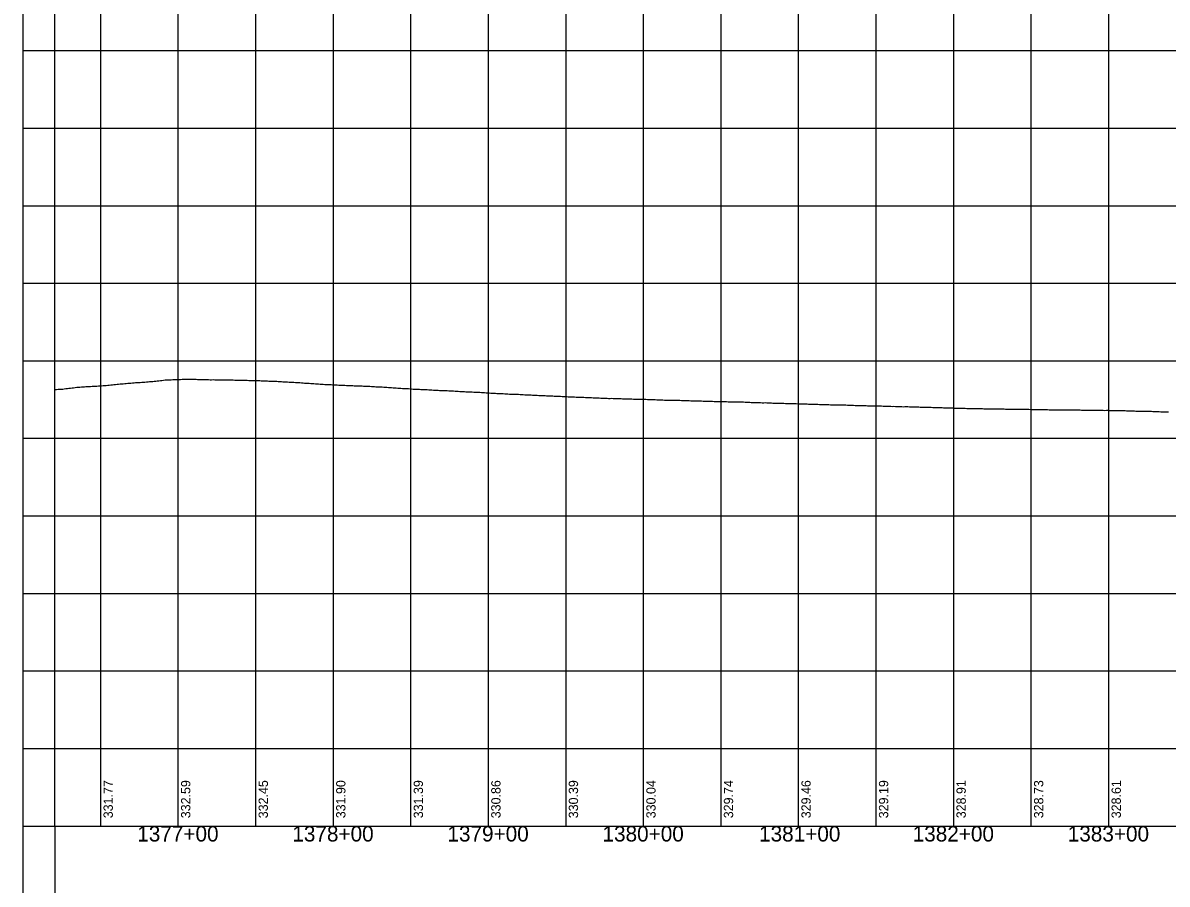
# Model space of a CAD drawing. Extents: x -90830 to 2015517, y -20856 to 836331.
# Drawn here: x 9623 to 10361, y 20025 to 20581 of the extents above; entities that cross this region are included whole.
import ezdxf

# ---------------------------------------------------------------- set-up
doc = ezdxf.new("R2010")
doc.units = 0
for name, color, linetype in [('Level 1', 7, 'Continuous'), ('RD_DDB_Profile_EX', 7, 'Continuous'), ('RD_DDB_StaTX', 7, 'Continuous'), ('RD_DDB_StripGrade', 7, 'Continuous'), ('RD_GPK_Profile_Cell', 7, 'Continuous'), ('RD_SHT_MatchLine', 7, 'Continuous')]:
    doc.layers.add(name, color=color, linetype=linetype)

msp = doc.modelspace()

# ---------------------------------------------------------------- linework, layer by layer
at = {"layer": 'Level 1'}
for p, q in [((9623.46, 21062.87), (9623.46, 20562.87)), ((9673.46, 21062.87), (9673.46, 20562.87)), ((9723.46, 21062.87), (9723.46, 20562.87)), ((9773.46, 21062.87), (9773.46, 20562.87)), ((9823.46, 21062.87), (9823.46, 20562.87)), ((9873.46, 21062.87), (9873.46, 20562.87)), ((9923.46, 21062.87), (9923.46, 20562.87)), ((9973.46, 21062.87), (9973.46, 20562.87)), ((10023.46, 21062.87), (10023.46, 20562.87)), ((10073.46, 21062.87), (10073.46, 20562.87)), ((10123.46, 21062.87), (10123.46, 20562.87)), ((10173.46, 21062.87), (10173.46, 20562.87)), ((10223.46, 21062.87), (10223.46, 20562.87)), ((10273.46, 21062.87), (10273.46, 20562.87)), ((10323.46, 21062.87), (10323.46, 20562.87)), ((9623.46, 20562.87), (11223.46, 20562.87)), ((9623.46, 20562.87), (11223.46, 20562.87)), ((9623.46, 20562.87), (9623.46, 20062.87)), ((9673.46, 20562.87), (9673.46, 20062.87)), ((9723.46, 20562.87), (9723.46, 20062.87)), ((9773.46, 20562.87), (9773.46, 20062.87)), ((9823.46, 20562.87), (9823.46, 20062.87)), ((9873.46, 20562.87), (9873.46, 20062.87)), ((9923.46, 20562.87), (9923.46, 20062.87)), ((9973.46, 20562.87), (9973.46, 20062.87)), ((10023.46, 20562.87), (10023.46, 20062.87)), ((10073.46, 20562.87), (10073.46, 20062.87)), ((10123.46, 20562.87), (10123.46, 20062.87)), ((10173.46, 20562.87), (10173.46, 20062.87)), ((10223.46, 20562.87), (10223.46, 20062.87)), ((10273.46, 20562.87), (10273.46, 20062.87)), ((10323.46, 20562.87), (10323.46, 20062.87)), ((9623.46, 20512.87), (11223.46, 20512.87)), ((9623.46, 20462.87), (11223.46, 20462.87)), ((9623.46, 20412.87), (11223.46, 20412.87)), ((9623.46, 20362.87), (11223.46, 20362.87)), ((9623.46, 20312.87), (11223.46, 20312.87)), ((9623.46, 20262.87), (11223.46, 20262.87)), ((9623.46, 20212.87), (11223.46, 20212.87)), ((9623.46, 20162.87), (11223.46, 20162.87)), ((9623.46, 20112.87), (11223.46, 20112.87)), ((9623.46, 20062.87), (11223.46, 20062.87))]:
    msp.add_line(p, q, dxfattribs=at)
at = {"layer": 'RD_DDB_Profile_EX'}
for points in [[(9644.15, 20344.38), (9645.15, 20344.44), (9646.15, 20344.5), (9647.15, 20344.55), (9648.15, 20344.61), (9649.15, 20344.62), (9650.15, 20344.74), (9651.15, 20344.89), (9652.15, 20344.96), (9653.15, 20345.12), (9654.15, 20345.28), (9655.15, 20345.38), (9656.15, 20345.52), (9657.15, 20345.63), (9658.15, 20345.77), (9659.15, 20345.84), (9660.15, 20345.93), (9661.15, 20346.03), (9662.15, 20346.08), (9663.15, 20346.13), (9664.15, 20346.21), (9665.15, 20346.27), (9666.15, 20346.31), (9667.15, 20346.36), (9668.15, 20346.44), (9669.15, 20346.51), (9670.15, 20346.56), (9671.15, 20346.6), (9672.15, 20346.66), (9673.15, 20346.7), (9674.15, 20346.79), (9675.15, 20346.85), (9676.15, 20346.89), (9677.15, 20346.98), (9678.15, 20347.07), (9679.15, 20347.17), (9680.15, 20347.27), (9681.15, 20347.37), (9682.15, 20347.51), (9683.15, 20347.65), (9684.15, 20347.76), (9685.15, 20347.86), (9686.15, 20347.95), (9687.15, 20348.01), (9688.15, 20348.08), (9689.15, 20348.2), (9690.15, 20348.29), (9691.15, 20348.37), (9692.15, 20348.47), (9693.15, 20348.5), (9694.15, 20348.57), (9695.15, 20348.66), (9696.15, 20348.76), (9697.15, 20348.82), (9698.15, 20348.87), (9699.15, 20348.96), (9700.15, 20349.06), (9701.15, 20349.13), (9702.15, 20349.14), (9703.15, 20349.21), (9704.15, 20349.31), (9705.15, 20349.4), (9706.15, 20349.53), (9707.15, 20349.6), (9708.15, 20349.69), (9709.15, 20349.75), (9710.15, 20349.88), (9711.15, 20350.02), (9712.15, 20350.13), (9713.15, 20350.22), (9714.15, 20350.34), (9715.15, 20350.48), (9716.15, 20350.54), (9717.15, 20350.59), (9718.15, 20350.64), (9719.15, 20350.66), (9720.15, 20350.74), (9721.15, 20350.8), (9722.15, 20350.81), (9723.15, 20350.81), (9724.15, 20350.77), (9725.15, 20350.8), (9726.15, 20351.02), (9727.15, 20351.08), (9728.15, 20351.09), (9729.15, 20351.06), (9730.15, 20351.06), (9731.15, 20351.03), (9732.15, 20350.98), (9733.15, 20350.98), (9734.15, 20350.94), (9735.15, 20350.93), (9736.15, 20350.89), (9737.15, 20350.82), (9738.15, 20350.82), (9739.15, 20350.88), (9740.15, 20350.86), (9741.15, 20350.78), (9742.15, 20350.74), (9743.15, 20350.7), (9744.15, 20350.66)], [(9744.15, 20350.66), (9745.15, 20350.66), (9746.15, 20350.7), (9747.15, 20350.68), (9748.15, 20350.67), (9749.15, 20350.64), (9750.15, 20350.56), (9751.15, 20350.55), (9752.15, 20350.59), (9753.15, 20350.6), (9754.15, 20350.6), (9755.15, 20350.56), (9756.15, 20350.55), (9757.15, 20350.55), (9758.15, 20350.54), (9759.15, 20350.51), (9760.15, 20350.46), (9761.15, 20350.46), (9762.15, 20350.42), (9763.15, 20350.41), (9764.15, 20350.4), (9765.15, 20350.37), (9766.15, 20350.31), (9767.15, 20350.29), (9768.15, 20350.3), (9769.15, 20350.23), (9770.15, 20350.17), (9771.15, 20350.17), (9772.15, 20350.16), (9773.15, 20350.13), (9774.15, 20350.12), (9775.15, 20350.08), (9776.15, 20350.06), (9777.15, 20350.02), (9778.15, 20349.98), (9779.15, 20349.93), (9780.15, 20349.89), (9781.15, 20349.85), (9782.15, 20349.8), (9783.15, 20349.75), (9784.15, 20349.7), (9785.15, 20349.65), (9786.15, 20349.63), (9787.15, 20349.62), (9788.15, 20349.58), (9789.15, 20349.51), (9790.15, 20349.44), (9791.15, 20349.39), (9792.15, 20349.33), (9793.15, 20349.28), (9794.15, 20349.2), (9795.15, 20349.16), (9796.15, 20349.12), (9797.15, 20349.09), (9798.15, 20348.99), (9799.15, 20348.93), (9800.15, 20348.89), (9801.15, 20348.83), (9802.15, 20348.78), (9803.15, 20348.7), (9804.15, 20348.6), (9805.15, 20348.49), (9806.15, 20348.44), (9807.15, 20348.41), (9808.15, 20348.35), (9809.15, 20348.3), (9810.15, 20348.22), (9811.15, 20348.12), (9812.15, 20348.07), (9813.15, 20348.01), (9814.15, 20347.93), (9815.15, 20347.85), (9816.15, 20347.77), (9817.15, 20347.72), (9818.15, 20347.67), (9819.15, 20347.61), (9820.15, 20347.53), (9821.15, 20347.49), (9822.15, 20347.48), (9823.15, 20347.41), (9824.15, 20347.32), (9825.15, 20347.29), (9826.15, 20347.27), (9827.15, 20347.22), (9828.15, 20347.17), (9829.15, 20347.12), (9830.15, 20347.09), (9831.15, 20347.07), (9832.15, 20347.02), (9833.15, 20346.98), (9834.15, 20346.97), (9835.15, 20346.92), (9836.15, 20346.86), (9837.15, 20346.81), (9838.15, 20346.76), (9839.15, 20346.73), (9840.15, 20346.71), (9841.15, 20346.66), (9842.15, 20346.61), (9843.15, 20346.58), (9844.15, 20346.56)], [(9844.15, 20346.56), (9845.15, 20346.51), (9846.15, 20346.46), (9847.15, 20346.41), (9848.15, 20346.36), (9849.15, 20346.31), (9850.15, 20346.24), (9851.15, 20346.16), (9852.15, 20346.09), (9853.15, 20346.01), (9854.15, 20345.97), (9855.15, 20345.96), (9856.15, 20345.91), (9857.15, 20345.84), (9858.15, 20345.76), (9859.15, 20345.69), (9860.15, 20345.62), (9861.15, 20345.58), (9862.15, 20345.46), (9863.15, 20345.42), (9864.15, 20345.39), (9865.15, 20345.31), (9866.15, 20345.26), (9867.15, 20345.19), (9868.15, 20345.09), (9869.15, 20345.01), (9870.15, 20344.97), (9871.15, 20344.96), (9872.15, 20344.91), (9873.15, 20344.84), (9874.15, 20344.74), (9875.15, 20344.66), (9876.15, 20344.61), (9877.15, 20344.57), (9878.15, 20344.56), (9879.15, 20344.49), (9880.15, 20344.41), (9881.15, 20344.37), (9882.15, 20344.36), (9883.15, 20344.31), (9884.15, 20344.26), (9885.15, 20344.19), (9886.15, 20344.11), (9887.15, 20344.06), (9888.15, 20344.01), (9889.15, 20343.94), (9890.15, 20343.87), (9891.15, 20343.84), (9892.15, 20343.76), (9893.15, 20343.72), (9894.15, 20343.72), (9895.15, 20343.71), (9896.15, 20343.66), (9897.15, 20343.61), (9898.15, 20343.54), (9899.15, 20343.46), (9900.15, 20343.42), (9901.15, 20343.39), (9902.15, 20343.31), (9903.15, 20343.26), (9904.15, 20343.21), (9905.15, 20343.16), (9906.15, 20343.11), (9907.15, 20343.06), (9908.15, 20343.01), (9909.15, 20342.94), (9910.15, 20342.86), (9911.15, 20342.82), (9912.15, 20342.81), (9913.15, 20342.76), (9914.15, 20342.71), (9915.15, 20342.66), (9916.15, 20342.61), (9917.15, 20342.56), (9918.15, 20342.52), (9919.15, 20342.49), (9920.15, 20342.39), (9921.15, 20342.31), (9922.15, 20342.26), (9923.15, 20342.19), (9924.15, 20342.11), (9925.15, 20342.06), (9926.15, 20342.01), (9927.15, 20341.96), (9928.15, 20341.91), (9929.15, 20341.86), (9930.15, 20341.81), (9931.15, 20341.76), (9932.15, 20341.71), (9933.15, 20341.66), (9934.15, 20341.59), (9935.15, 20341.52), (9936.15, 20341.49), (9937.15, 20341.41), (9938.15, 20341.39), (9939.15, 20341.41), (9940.15, 20341.34), (9941.15, 20341.27), (9942.15, 20341.29), (9943.15, 20341.27), (9944.15, 20341.14)], [(9944.15, 20341.14), (9945.15, 20341.07), (9946.15, 20341.06), (9947.15, 20341.01), (9948.15, 20340.94), (9949.15, 20340.87), (9950.15, 20340.86), (9951.15, 20340.81), (9952.15, 20340.77), (9953.15, 20340.76), (9954.15, 20340.71), (9955.15, 20340.64), (9956.15, 20340.56), (9957.15, 20340.52), (9958.15, 20340.52), (9959.15, 20340.49), (9960.15, 20340.4), (9961.15, 20340.35), (9962.15, 20340.3), (9963.15, 20340.27), (9964.15, 20340.25), (9965.15, 20340.2), (9966.15, 20340.15), (9967.15, 20340.1), (9968.15, 20340.06), (9969.15, 20340.04), (9970.15, 20339.98), (9971.15, 20339.91), (9972.15, 20339.9), (9973.15, 20339.83), (9974.15, 20339.74), (9975.15, 20339.69), (9976.15, 20339.64), (9977.15, 20339.61), (9978.15, 20339.59), (9979.15, 20339.54), (9980.15, 20339.49), (9981.15, 20339.46), (9982.15, 20339.46), (9983.15, 20339.45), (9984.15, 20339.38), (9985.15, 20339.3), (9986.15, 20339.25), (9987.15, 20339.21), (9988.15, 20339.19), (9989.15, 20339.14), (9990.15, 20339.09), (9991.15, 20339.06), (9992.15, 20339.04), (9993.15, 20338.99), (9994.15, 20338.96), (9995.15, 20338.93), (9996.15, 20338.83), (9997.15, 20338.75), (9998.15, 20338.71), (9999.15, 20338.71), (10000.15, 20338.68), (10001.15, 20338.62), (10002.15, 20338.63), (10003.15, 20338.65), (10004.15, 20338.6), (10005.15, 20338.57), (10006.15, 20338.55), (10007.15, 20338.51), (10008.15, 20338.47), (10009.15, 20338.46), (10010.15, 20338.41), (10011.15, 20338.39), (10012.15, 20338.41), (10013.15, 20338.38), (10014.15, 20338.34), (10015.15, 20338.26), (10016.15, 20338.22), (10017.15, 20338.18), (10018.15, 20338.18), (10019.15, 20338.18), (10020.15, 20338.18), (10021.15, 20338.18), (10022.15, 20338.15), (10023.15, 20338.06), (10024.15, 20338.03), (10025.15, 20338.01), (10026.15, 20337.96), (10027.15, 20337.93), (10028.15, 20337.91), (10029.15, 20337.87), (10030.15, 20337.83), (10031.15, 20337.81), (10032.15, 20337.78), (10033.15, 20337.76), (10034.15, 20337.72), (10035.15, 20337.67), (10036.15, 20337.62), (10037.15, 20337.57), (10038.15, 20337.52), (10039.15, 20337.47), (10040.15, 20337.44), (10041.15, 20337.44), (10042.15, 20337.44), (10043.15, 20337.42), (10044.15, 20337.39)], [(10044.15, 20337.39), (10045.15, 20337.39), (10046.15, 20337.39), (10047.15, 20337.37), (10048.15, 20337.32), (10049.15, 20337.27), (10050.15, 20337.24), (10051.15, 20337.23), (10052.15, 20337.22), (10053.15, 20337.17), (10054.15, 20337.12), (10055.15, 20337.09), (10056.15, 20337.07), (10057.15, 20337.03), (10058.15, 20337.03), (10059.15, 20337.03), (10060.15, 20337.03), (10061.15, 20337), (10062.15, 20336.91), (10063.15, 20336.88), (10064.15, 20336.86), (10065.15, 20336.82), (10066.15, 20336.8), (10067.15, 20336.77), (10068.15, 20336.75), (10069.15, 20336.69), (10070.15, 20336.66), (10071.15, 20336.65), (10072.15, 20336.6), (10073.15, 20336.58), (10074.15, 20336.62), (10075.15, 20336.59), (10076.15, 20336.52), (10077.15, 20336.5), (10078.15, 20336.45), (10079.15, 20336.42), (10080.15, 20336.38), (10081.15, 20336.32), (10082.15, 20336.31), (10083.15, 20336.31), (10084.15, 20336.31), (10085.15, 20336.33), (10086.15, 20336.36), (10087.15, 20336.35), (10088.15, 20336.32), (10089.15, 20336.24), (10090.15, 20336.18), (10091.15, 20336.13), (10092.15, 20336.09), (10093.15, 20336.06), (10094.15, 20336.05), (10095.15, 20336), (10096.15, 20335.97), (10097.15, 20335.96), (10098.15, 20335.92), (10099.15, 20335.9), (10100.15, 20335.83), (10101.15, 20335.84), (10102.15, 20335.86), (10103.15, 20335.81), (10104.15, 20335.76), (10105.15, 20335.71), (10106.15, 20335.67), (10107.15, 20335.62), (10108.15, 20335.58), (10109.15, 20335.57), (10110.15, 20335.55), (10111.15, 20335.57), (10112.15, 20335.53), (10113.15, 20335.52), (10114.15, 20335.47), (10115.15, 20335.42), (10116.15, 20335.37), (10117.15, 20335.32), (10118.15, 20335.29), (10119.15, 20335.27), (10120.15, 20335.24), (10121.15, 20335.24), (10122.15, 20335.22), (10123.15, 20335.19), (10124.15, 20335.17), (10125.15, 20335.14), (10126.15, 20335.12), (10127.15, 20335.07), (10128.15, 20335.03), (10129.15, 20335.02), (10130.15, 20334.97), (10131.15, 20334.92), (10132.15, 20334.88), (10133.15, 20334.88), (10134.15, 20334.88), (10135.15, 20334.86), (10136.15, 20334.81), (10137.15, 20334.76), (10138.15, 20334.75), (10139.15, 20334.76), (10140.15, 20334.73), (10141.15, 20334.73), (10142.15, 20334.71), (10143.15, 20334.65), (10144.15, 20334.56)], [(10144.15, 20334.56), (10145.15, 20334.53), (10146.15, 20334.53), (10147.15, 20334.51), (10148.15, 20334.48), (10149.15, 20334.48), (10150.15, 20334.48), (10151.15, 20334.46), (10152.15, 20334.42), (10153.15, 20334.41), (10154.15, 20334.37), (10155.15, 20334.35), (10156.15, 20334.3), (10157.15, 20334.27), (10158.15, 20334.24), (10159.15, 20334.16), (10160.15, 20334.12), (10161.15, 20334.12), (10162.15, 20334.11), (10163.15, 20334.07), (10164.15, 20334.06), (10165.15, 20334.02), (10166.15, 20334.02), (10167.15, 20333.98), (10168.15, 20333.89), (10169.15, 20333.91), (10170.15, 20333.87), (10171.15, 20333.87), (10172.15, 20333.86), (10173.15, 20333.81), (10174.15, 20333.79), (10175.15, 20333.82), (10176.15, 20333.79), (10177.15, 20333.71), (10178.15, 20333.69), (10179.15, 20333.69), (10180.15, 20333.61), (10181.15, 20333.56), (10182.15, 20333.52), (10183.15, 20333.51), (10184.15, 20333.49), (10185.15, 20333.51), (10186.15, 20333.46), (10187.15, 20333.41), (10188.15, 20333.37), (10189.15, 20333.36), (10190.15, 20333.31), (10191.15, 20333.27), (10192.15, 20333.29), (10193.15, 20333.32), (10194.15, 20333.31), (10195.15, 20333.27), (10196.15, 20333.26), (10197.15, 20333.21), (10198.15, 20333.17), (10199.15, 20333.17), (10200.15, 20333.17), (10201.15, 20333.14), (10202.15, 20333.06), (10203.15, 20333.02), (10204.15, 20333.01), (10205.15, 20332.97), (10206.15, 20332.97), (10207.15, 20332.95), (10208.15, 20332.92), (10209.15, 20332.9), (10210.15, 20332.83), (10211.15, 20332.75), (10212.15, 20332.71), (10213.15, 20332.71), (10214.15, 20332.72), (10215.15, 20332.73), (10216.15, 20332.64), (10217.15, 20332.6), (10218.15, 20332.55), (10219.15, 20332.52), (10220.15, 20332.54), (10221.15, 20332.56), (10222.15, 20332.51), (10223.15, 20332.46), (10224.15, 20332.41), (10225.15, 20332.36), (10226.15, 20332.33), (10227.15, 20332.33), (10228.15, 20332.31), (10229.15, 20332.26), (10230.15, 20332.23), (10231.15, 20332.21), (10232.15, 20332.16), (10233.15, 20332.13), (10234.15, 20332.13), (10235.15, 20332.14), (10236.15, 20332.16), (10237.15, 20332.11), (10238.15, 20332.08), (10239.15, 20332.07), (10240.15, 20332.07), (10241.15, 20332.06), (10242.15, 20332.01), (10243.15, 20331.98), (10244.15, 20331.96)], [(10244.15, 20331.96), (10245.15, 20331.94), (10246.15, 20331.96), (10247.15, 20331.9), (10248.15, 20331.83), (10249.15, 20331.83), (10250.15, 20331.83), (10251.15, 20331.83), (10252.15, 20331.82), (10253.15, 20331.78), (10254.15, 20331.79), (10255.15, 20331.83), (10256.15, 20331.81), (10257.15, 20331.75), (10258.15, 20331.68), (10259.15, 20331.68), (10260.15, 20331.68), (10261.15, 20331.67), (10262.15, 20331.68), (10263.15, 20331.65), (10264.15, 20331.58), (10265.15, 20331.59), (10266.15, 20331.64), (10267.15, 20331.66), (10268.15, 20331.61), (10269.15, 20331.59), (10270.15, 20331.61), (10271.15, 20331.58), (10272.15, 20331.58), (10273.15, 20331.55), (10274.15, 20331.48), (10275.15, 20331.48), (10276.15, 20331.48), (10277.15, 20331.46), (10278.15, 20331.43), (10279.15, 20331.42), (10280.15, 20331.39), (10281.15, 20331.41), (10282.15, 20331.38), (10283.15, 20331.38), (10284.15, 20331.36), (10285.15, 20331.3), (10286.15, 20331.24), (10287.15, 20331.29), (10288.15, 20331.3), (10289.15, 20331.25), (10290.15, 20331.28), (10291.15, 20331.26), (10292.15, 20331.23), (10293.15, 20331.21), (10294.15, 20331.18), (10295.15, 20331.19), (10296.15, 20331.22), (10297.15, 20331.22), (10298.15, 20331.21), (10299.15, 20331.18), (10300.15, 20331.19), (10301.15, 20331.23), (10302.15, 20331.21), (10303.15, 20331.17), (10304.15, 20331.18), (10305.15, 20331.16), (10306.15, 20331.1), (10307.15, 20331.03), (10308.15, 20331.05), (10309.15, 20331.08), (10310.15, 20331.07), (10311.15, 20331.03), (10312.15, 20331.03), (10313.15, 20331.03), (10314.15, 20331.03), (10315.15, 20331.02), (10316.15, 20330.99), (10317.15, 20330.97), (10318.15, 20330.95), (10319.15, 20330.97), (10320.15, 20330.93), (10321.15, 20330.91), (10322.15, 20330.94), (10323.15, 20330.92), (10324.15, 20330.89), (10325.15, 20330.89), (10326.15, 20330.89), (10327.15, 20330.87), (10328.15, 20330.84), (10329.15, 20330.82), (10330.15, 20330.77), (10331.15, 20330.74), (10332.15, 20330.73), (10333.15, 20330.73), (10334.15, 20330.72), (10335.15, 20330.67), (10336.15, 20330.62), (10337.15, 20330.59), (10338.15, 20330.57), (10339.15, 20330.52), (10340.15, 20330.49), (10341.15, 20330.47), (10342.15, 20330.42), (10343.15, 20330.4), (10344.15, 20330.42)], [(10344.15, 20330.42), (10345.15, 20330.37), (10346.15, 20330.33), (10347.15, 20330.33), (10348.15, 20330.33), (10349.15, 20330.33), (10350.15, 20330.33), (10351.15, 20330.31), (10352.15, 20330.25), (10353.15, 20330.18), (10354.15, 20330.16), (10355.15, 20330.11), (10356.15, 20330.07), (10357.15, 20330.02), (10358.15, 20329.98), (10359.15, 20329.98), (10360.15, 20329.98), (10361.15, 20329.97), (10362.15, 20329.95)]]:
    msp.add_lwpolyline(points, dxfattribs=at)
at = {"layer": 'RD_GPK_Profile_Cell'}
for q in [(9644.15, 21312.87), (12444.15, 20062.87), (9644.15, 18812.87)]:
    msp.add_line((9644.15, 20062.87), q, dxfattribs=at)
at = {"layer": 'RD_SHT_MatchLine'}
for p, q in [((9623.46, 20062.87), (9623.46, 19425.67)), ((9644.15, 20062.87), (9644.15, 19425.67))]:
    msp.add_line(p, q, dxfattribs=at)

# ---------------------------------------------------------------- texts
at = {"layer": 'RD_DDB_StaTX'}
for s, p in [('1377+00', (9697.21, 20052.87)), ('1378+00', (9797.21, 20052.87)), ('1379+00', (9897.21, 20052.87)), ('1380+00', (9997.21, 20052.87)), ('1381+00', (10098.17, 20052.87)), ('1382+00', (10197.21, 20052.87)), ('1383+00', (10297.21, 20052.87))]:
    msp.add_text(s, height=10, dxfattribs=at).set_placement(p)
at = {"layer": 'RD_DDB_StripGrade'}
for s, p in [('331.77', (9681.46, 20067.87)), ('332.59', (9731.46, 20067.87)), ('332.45', (9781.46, 20067.87)), ('331.90', (9831.46, 20067.87)), ('331.39', (9881.46, 20067.87)), ('330.86', (9931.46, 20067.87)), ('330.39', (9981.46, 20067.87)), ('330.04', (10031.46, 20067.87)), ('329.74', (10081.46, 20067.87)), ('329.46', (10131.46, 20067.87)), ('329.19', (10181.46, 20067.87)), ('328.91', (10231.46, 20067.87)), ('328.73', (10281.46, 20067.87)), ('328.61', (10331.46, 20067.87))]:
    msp.add_text(s, height=6, rotation=90, dxfattribs=at).set_placement(p)

doc.saveas('drawing.dxf')
